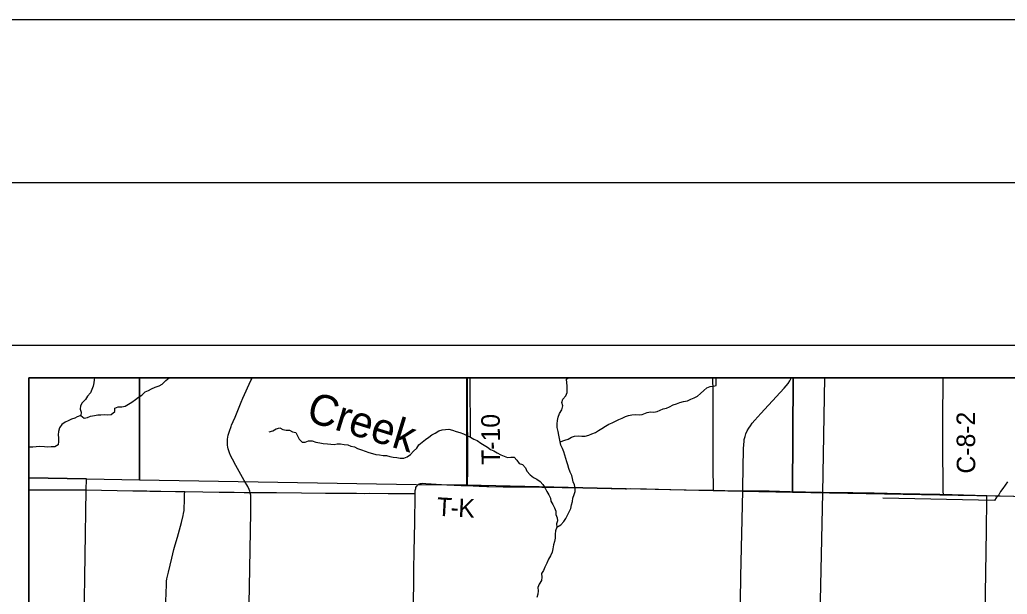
# Model space of a CAD drawing. Extents: x -21.7 to 34, y 0 to 22.
# Drawn here: x 23.488 to 26.522, y 20.235 to 22 of the extents above; entities that cross this region are included whole.
import ezdxf

# ---------------------------------------------------------------- set-up
doc = ezdxf.new("R2010")
doc.units = 0
for name, color, linetype in [('Default', 7, 'Continuous'), ('GM_X_County_Road', 7, 'Continuous'), ('GM_X_County_Road_Text', 7, 'Continuous'), ('GM_X_Interchange_Ramps', 7, 'Continuous'), ('GM_X_Minor_River', 7, 'Continuous'), ('GM_X_Minor_River_Text', 7, 'Continuous'), ('GM_X_Rail_Line', 7, 'Continuous'), ('GM_X_State_Route', 7, 'Continuous'), ('GM_X_Township_Road', 7, 'Continuous'), ('GM_X_Township_Road_Text', 7, 'Continuous'), ('SH_Border', 7, 'Continuous'), ('SH_Cut_Line', 7, 'Continuous'), ('SH_Data', 7, 'Continuous')]:
    doc.layers.add(name, color=color, linetype=linetype)

msp = doc.modelspace()

# ---------------------------------------------------------------- linework, layer by layer
at = {"layer": 'Default'}
for points in [[(23.856, 20.9), (23.5167, 20.9), (23.5167, 20.5927), (23.6932, 20.5898), (23.8561, 20.5869)], [(24.8623, 20.9), (23.856, 20.9), (23.8561, 20.5869), (24.7067, 20.5725), (24.8624, 20.5713)], [(25.8643, 20.9), (24.8623, 20.9), (24.8624, 20.5713), (25.7076, 20.5517), (25.8621, 20.5483)], [(26.8675, 20.9), (25.8643, 20.9), (25.8621, 20.5483), (26.7115, 20.5335), (26.8676, 20.5312)], [(23.5167, 20.5927), (23.5167, 20.5562), (23.693, 20.5545), (23.6932, 20.5898)], [(23.5167, 20.5562), (23.5167, 19.5535), (23.6774, 19.5512), (23.693, 20.5545)]]:
    msp.add_lwpolyline(points, close=True, dxfattribs=at)
at = {"layer": 'GM_X_County_Road'}
for points in [[(24.1961, 20.5478), (24.195, 20.5512), (24.1928, 20.5571), (24.1887, 20.5656), (24.1779, 20.5848), (24.1519, 20.6308), (24.1416, 20.6499), (24.136, 20.661), (24.1324, 20.6695), (24.1305, 20.6753), (24.1289, 20.6813), (24.1276, 20.6873), (24.1268, 20.6934), (24.1264, 20.6995), (24.1264, 20.7057), (24.1267, 20.7118), (24.1275, 20.7179), (24.1288, 20.7239), (24.1324, 20.7359), (24.1376, 20.7499), (24.1389, 20.7547), (24.1439, 20.7656), (24.1499, 20.7789), (24.1582, 20.7996), (24.1682, 20.8247), (24.1743, 20.8369), (24.1987, 20.8912), (24.201, 20.8971), (24.2022, 20.9)], [(26.326, 20.5418), (26.3254, 20.5503), (26.325, 20.5565), (26.3242, 20.6933), (26.3241, 20.768), (26.325, 20.9)], [(24.7034, 20.5441), (24.7034, 20.5493), (24.7033, 20.551), (24.7035, 20.5536), (24.7039, 20.5566), (24.7048, 20.5598), (24.7058, 20.5629), (24.7072, 20.5658), (24.709, 20.5685), (24.7103, 20.5698)], [(24.7103, 20.5698), (24.7113, 20.5709), (24.7139, 20.5728), (24.7169, 20.5742), (24.72, 20.5751), (24.7232, 20.5756), (24.7263, 20.5758), (24.7357, 20.5756), (24.8003, 20.5714), (24.8443, 20.5695), (24.8641, 20.5686)], [(23.5167, 20.5567), (23.6055, 20.556), (23.6583, 20.5553), (23.7391, 20.5543), (23.8355, 20.5527), (23.8634, 20.5524), (23.8789, 20.5523), (23.8882, 20.5521), (23.8913, 20.552), (23.9222, 20.5515), (23.9673, 20.5507), (23.9953, 20.5503)], [(23.9953, 20.5503), (24.0511, 20.5497), (24.1008, 20.549), (24.1253, 20.5485), (24.147, 20.5482), (24.178, 20.548), (24.1961, 20.5478)], [(24.1832, 19.6003), (24.1843, 19.6442), (24.1852, 19.7126), (24.186, 19.7685), (24.187, 19.8244), (24.1894, 19.9642), (24.1905, 20.0482), (24.1917, 20.1134), (24.194, 20.2563), (24.1969, 20.4303), (24.198, 20.4862), (24.1988, 20.5298), (24.1984, 20.5361), (24.198, 20.5392), (24.1968, 20.5453), (24.1961, 20.5478)], [(24.1961, 20.5478), (24.237, 20.5475), (24.2769, 20.5471), (24.3539, 20.5462), (24.4276, 20.5459), (24.4552, 20.5456), (24.5228, 20.5453), (24.5478, 20.5449), (24.5643, 20.5452), (24.6201, 20.545), (24.6461, 20.5445), (24.6953, 20.5442), (24.7034, 20.5441)], [(24.8641, 20.5686), (24.8816, 20.5679), (24.8938, 20.5678), (24.8998, 20.5675), (24.9055, 20.567), (24.9237, 20.5665), (24.9268, 20.5665), (24.9296, 20.5661), (24.9731, 20.5655), (25.0293, 20.5652), (25.2188, 20.5615), (25.3494, 20.559), (25.3525, 20.559), (25.3647, 20.5595), (25.3957, 20.559), (25.4144, 20.5584), (25.489, 20.5572), (25.5355, 20.5562), (25.6198, 20.5546)], [(25.6198, 20.5546), (25.6908, 20.5532), (25.7094, 20.5531)], [(25.7094, 20.5531), (25.7157, 20.5531), (25.7468, 20.5528), (25.7903, 20.5522), (25.8556, 20.5506), (25.9022, 20.5499), (25.9519, 20.5487), (26.0016, 20.548), (26.0482, 20.5472), (26.1135, 20.5465), (26.1943, 20.545), (26.2534, 20.5435), (26.3155, 20.542), (26.326, 20.5418)], [(26.326, 20.5418), (26.3528, 20.5413), (26.4584, 20.5382), (26.4593, 20.5382)], [(26.433, 19.5159), (26.434, 19.5982), (26.4362, 19.7226), (26.4372, 19.7662), (26.439, 19.8066), (26.4419, 19.8594), (26.447, 19.9526), (26.4512, 20.0334), (26.4559, 20.1203), (26.4565, 20.1421), (26.4565, 20.1607), (26.4554, 20.204), (26.4556, 20.2383), (26.4562, 20.3005), (26.4581, 20.4311), (26.4592, 20.5276), (26.4593, 20.5382)], [(26.4593, 20.5382), (26.5424, 20.5362), (26.7039, 20.5311), (26.7598, 20.5304), (26.8158, 20.5296), (26.8674, 20.5283)]]:
    msp.add_lwpolyline(points, dxfattribs=at)
at = {"layer": 'GM_X_Interchange_Ramps'}
msp.add_lwpolyline([(27.8768, 20.9), (23.5167, 20.9), (23.5167, 18.5138)], dxfattribs=at)
at = {"layer": 'GM_X_Minor_River'}
for p, q in [((24.8729, 20.7176), (24.8724, 20.9)), ((25.6283, 20.8768), (25.6281, 20.9))]:
    msp.add_line(p, q, dxfattribs=at)
for points in [[(23.7186, 20.9), (23.7172, 20.894), (23.7158, 20.8841), (23.7141, 20.8743), (23.7104, 20.8641), (23.7056, 20.8536), (23.697, 20.8439), (23.69, 20.8334), (23.6806, 20.8234), (23.6755, 20.8136), (23.6741, 20.8038), (23.6769, 20.7943), (23.6763, 20.784), (23.686, 20.7762), (23.6966, 20.7779), (23.7062, 20.7818), (23.7176, 20.7839), (23.7279, 20.7863), (23.7374, 20.7865), (23.7488, 20.7877), (23.759, 20.786), (23.7693, 20.7876), (23.7805, 20.7969), (23.7804, 20.8068), (23.7907, 20.8103), (23.8025, 20.8112), (23.8124, 20.8129), (23.8228, 20.8187), (23.8324, 20.825), (23.8436, 20.8331), (23.8537, 20.8408), (23.8637, 20.8467), (23.8741, 20.8567), (23.8837, 20.8614), (23.8937, 20.8657), (23.9048, 20.8712), (23.9163, 20.8751), (23.9263, 20.8809), (23.9372, 20.8921), (23.9476, 20.8998), (23.9484, 20.9)], [(25.1388, 20.4406), (25.1503, 20.4483), (25.16, 20.458), (25.166, 20.4681), (25.1708, 20.4779), (25.1763, 20.4884), (25.1811, 20.4989), (25.1833, 20.5098), (25.1866, 20.52), (25.1876, 20.5306), (25.1916, 20.5412), (25.1945, 20.551), (25.1944, 20.5612), (25.1923, 20.5708), (25.1887, 20.5803), (25.1867, 20.5906), (25.1843, 20.6002), (25.1799, 20.6097), (25.1757, 20.6216), (25.1725, 20.6323), (25.1693, 20.6419), (25.1658, 20.6522), (25.1626, 20.6625), (25.1598, 20.6725), (25.1559, 20.6832), (25.1512, 20.6931), (25.1484, 20.7031), (25.1471, 20.7137), (25.1447, 20.7233), (25.1427, 20.7351), (25.1399, 20.7469), (25.1394, 20.7583), (25.1405, 20.7689), (25.143, 20.7795), (25.147, 20.79), (25.1541, 20.802), (25.1567, 20.8134), (25.1543, 20.824), (25.1568, 20.8346), (25.1665, 20.8446), (25.1698, 20.8544), (25.17, 20.8651), (25.1699, 20.8753), (25.1694, 20.8848), (25.1685, 20.8955), (25.1734, 20.9)], [(25.1484, 20.7031), (25.1633, 20.7081), (25.1736, 20.7116), (25.1832, 20.7171), (25.1932, 20.7203), (25.2035, 20.7216), (25.2148, 20.7202), (25.2251, 20.7203), (25.2365, 20.7239), (25.2465, 20.7275), (25.2568, 20.7322), (25.2665, 20.7384), (25.2768, 20.7439), (25.2884, 20.7512), (25.298, 20.7574), (25.308, 20.7618), (25.3183, 20.7665), (25.3291, 20.7719), (25.3394, 20.7755), (25.3494, 20.7813), (25.359, 20.7838), (25.3693, 20.7862), (25.3807, 20.7875), (25.3909, 20.7861), (25.4004, 20.7874), (25.4165, 20.7935), (25.426, 20.7956), (25.4366, 20.7946), (25.4462, 20.7966), (25.4557, 20.801), (25.4653, 20.8046), (25.4749, 20.807), (25.4848, 20.811), (25.4956, 20.8172), (25.5059, 20.8204), (25.5166, 20.8239), (25.5277, 20.8275), (25.5395, 20.8295), (25.5502, 20.8342), (25.5602, 20.8385), (25.5702, 20.8432), (25.5802, 20.8513), (25.59, 20.861), (25.5996, 20.8695), (25.6096, 20.8731), (25.6202, 20.874), (25.6283, 20.8768)], [(23.6763, 20.784), (23.6649, 20.7801), (23.6579, 20.7761), (23.6479, 20.7729), (23.6376, 20.7682), (23.628, 20.7635), (23.618, 20.7569), (23.6101, 20.746), (23.6076, 20.7351), (23.6066, 20.7252), (23.6079, 20.7153), (23.608, 20.7043), (23.6062, 20.6945), (23.5962, 20.6879), (23.5848, 20.6874), (23.5742, 20.6865), (23.564, 20.6874), (23.5492, 20.6885), (23.5393, 20.6876), (23.529, 20.6867), (23.5184, 20.6866), (23.5167, 20.6864)], [(24.2552, 20.7336), (24.2655, 20.7368), (24.2767, 20.7433), (24.2874, 20.7465), (24.2971, 20.7414), (24.3073, 20.7392), (24.3168, 20.7394), (24.3266, 20.7343), (24.3367, 20.7321), (24.3422, 20.7214), (24.3465, 20.711), (24.3561, 20.7021), (24.3656, 20.7023), (24.376, 20.7066), (24.387, 20.706), (24.3979, 20.7019), (24.4104, 20.7001), (24.4209, 20.6984), (24.4338, 20.697), (24.444, 20.6956), (24.4539, 20.6954), (24.4638, 20.6974), (24.474, 20.6972), (24.4854, 20.6954), (24.4963, 20.6937), (24.5061, 20.6904), (24.5167, 20.6883), (24.5264, 20.6831), (24.5385, 20.6787), (24.5497, 20.6743), (24.5614, 20.6706), (24.5723, 20.6673), (24.5825, 20.6648), (24.5935, 20.6634), (24.6045, 20.6613), (24.6151, 20.661), (24.6252, 20.6578), (24.6358, 20.6557), (24.6468, 20.655), (24.657, 20.6533), (24.6688, 20.6534), (24.6787, 20.657), (24.6884, 20.6647), (24.6981, 20.6744), (24.7082, 20.6837), (24.7149, 20.6945), (24.7246, 20.7023), (24.735, 20.71), (24.745, 20.7178), (24.7547, 20.7251), (24.7647, 20.7302), (24.7758, 20.7372), (24.7858, 20.74), (24.796, 20.7413), (24.8063, 20.7418), (24.8184, 20.7389), (24.8289, 20.7349), (24.8402, 20.732), (24.8515, 20.7275), (24.862, 20.7227), (24.8729, 20.7176), (24.8834, 20.7113), (24.8939, 20.7069), (24.9047, 20.699), (24.9148, 20.6935), (24.9253, 20.6868), (24.935, 20.6801), (24.9448, 20.6761), (24.9552, 20.6698), (24.9665, 20.6635), (24.9762, 20.6587), (24.9868, 20.6554), (24.997, 20.656), (25.0077, 20.6565), (25.0158, 20.6468), (25.0227, 20.6368), (25.0329, 20.6331), (25.0422, 20.6231), (25.0461, 20.6131), (25.0568, 20.6019), (25.0669, 20.594), (25.077, 20.5885), (25.0871, 20.5815), (25.0952, 20.5718), (25.1029, 20.5614), (25.1076, 20.5502), (25.1134, 20.5402), (25.1189, 20.5306), (25.1202, 20.5211), (25.1264, 20.5111), (25.1311, 20.5008), (25.135, 20.4904), (25.1355, 20.4805), (25.1395, 20.4702), (25.1408, 20.4607), (25.1379, 20.4509), (25.1388, 20.4406), (25.1347, 20.4297), (25.1337, 20.4195), (25.1338, 20.4077), (25.1313, 20.3975)], [(26.5231, 20.5801), (26.5157, 20.57), (26.5083, 20.5603), (26.5019, 20.5502), (26.496, 20.5405), (26.4882, 20.5308), (26.4835, 20.5233)], [(26.4835, 20.5233), (26.1403, 20.5298)], [(25.1313, 20.3975), (25.1284, 20.3866), (25.1266, 20.3748), (25.1241, 20.3646), (25.1185, 20.3534), (25.1133, 20.3429), (25.1073, 20.3308), (25.1021, 20.3181), (25.0977, 20.3083), (25.0918, 20.2985), (25.0919, 20.2879), (25.0913, 20.2769), (25.0842, 20.2664), (25.0805, 20.2555), (25.081, 20.2453), (25.08, 20.2354), (25.0775, 20.2252)]]:
    msp.add_lwpolyline(points, dxfattribs=at)
at = {"layer": 'GM_X_Rail_Line'}
msp.add_lwpolyline([(25.8368, 14.1), (25.8424, 14.4841), (25.8672, 15.4825), (25.8776, 16.2603), (25.8795, 16.4862), (25.8906, 16.927), (25.8907, 16.9438), (25.8961, 17.4845), (25.9239, 18.7551), (25.935, 19.5978), (25.9554, 20.5461), (25.9616, 20.9)], dxfattribs=at)
at = {"layer": 'GM_X_State_Route'}
msp.add_lwpolyline([(25.7012, 20.1404), (25.7041, 20.2896), (25.7094, 20.5531), (25.7096, 20.564), (25.7119, 20.6821), (25.7125, 20.6946), (25.7135, 20.7039), (25.7145, 20.7101), (25.7167, 20.7192), (25.7196, 20.7282), (25.7234, 20.7368), (25.7279, 20.745), (25.7331, 20.7529), (25.7387, 20.7604), (25.7467, 20.77), (25.7655, 20.7908), (25.8246, 20.8547), (25.8373, 20.8683), (25.8433, 20.8754), (25.849, 20.8827), (25.8542, 20.8904), (25.8588, 20.8984), (25.8595, 20.9)], dxfattribs=at)
at = {"layer": 'GM_X_Township_Road'}
for points in [[(24.8641, 20.5686), (24.8643, 20.5761), (24.8649, 20.6134), (24.8651, 20.6942), (24.8641, 20.7719), (24.8639, 20.8341), (24.8638, 20.9)], [(25.6198, 20.5546), (25.6197, 20.5598), (25.6195, 20.566), (25.6191, 20.6157), (25.6191, 20.6901), (25.6189, 20.7646), (25.6183, 20.8577), (25.6178, 20.9)], [(24.7034, 20.5441), (24.7034, 20.5493), (24.7033, 20.551), (24.7035, 20.5536), (24.7039, 20.5566), (24.7048, 20.5598), (24.7058, 20.5629), (24.7072, 20.5658), (24.709, 20.5685), (24.7103, 20.5698)], [(24.7103, 20.5698), (24.7113, 20.5709), (24.7139, 20.5728), (24.7169, 20.5742), (24.72, 20.5751), (24.7232, 20.5756), (24.7263, 20.5758), (24.7357, 20.5756), (24.8003, 20.5714), (24.8443, 20.5695), (24.8641, 20.5686)], [(23.5167, 20.5567), (23.6055, 20.556), (23.6583, 20.5553), (23.7391, 20.5543), (23.8355, 20.5527), (23.8634, 20.5524), (23.8789, 20.5523), (23.8882, 20.5521), (23.8913, 20.552), (23.9222, 20.5515), (23.9673, 20.5507), (23.9953, 20.5503)], [(23.9377, 20.2094), (23.9387, 20.2422), (23.9392, 20.2604), (23.9395, 20.2679), (23.9398, 20.2756), (23.9406, 20.2828), (23.9426, 20.2908), (23.9452, 20.3031), (23.9552, 20.3454), (23.9622, 20.3724), (23.9663, 20.3871), (23.9727, 20.4108), (23.9855, 20.4556), (23.9909, 20.4767), (23.992, 20.4828), (23.9932, 20.4922), (23.9937, 20.5015), (23.9943, 20.5202), (23.995, 20.5419), (23.9953, 20.5503)], [(23.9953, 20.5503), (24.0511, 20.5497), (24.1008, 20.549), (24.1253, 20.5485), (24.147, 20.5482), (24.178, 20.548), (24.1961, 20.5478)], [(24.1961, 20.5478), (24.237, 20.5475), (24.2769, 20.5471), (24.3539, 20.5462), (24.4276, 20.5459), (24.4552, 20.5456), (24.5228, 20.5453), (24.5478, 20.5449), (24.5643, 20.5452), (24.6201, 20.545), (24.6461, 20.5445), (24.6953, 20.5442), (24.7034, 20.5441)], [(24.69, 19.7638), (24.69, 19.7731), (24.6917, 19.882), (24.6937, 20.0126), (24.6988, 20.2673), (24.6995, 20.3171), (24.7004, 20.3606), (24.7013, 20.4166), (24.7021, 20.4508), (24.7034, 20.5441)], [(24.8641, 20.5686), (24.8816, 20.5679), (24.8938, 20.5678), (24.8998, 20.5675), (24.9055, 20.567), (24.9237, 20.5665), (24.9268, 20.5665), (24.9296, 20.5661), (24.9731, 20.5655), (25.0293, 20.5652), (25.2188, 20.5615), (25.3494, 20.559), (25.3525, 20.559), (25.3647, 20.5595), (25.3957, 20.559), (25.4144, 20.5584), (25.489, 20.5572), (25.5355, 20.5562), (25.6198, 20.5546)], [(25.6198, 20.5546), (25.6908, 20.5532), (25.7094, 20.5531)], [(25.7094, 20.5531), (25.7157, 20.5531), (25.7468, 20.5528), (25.7903, 20.5522), (25.8556, 20.5506), (25.9022, 20.5499), (25.9519, 20.5487), (26.0016, 20.548), (26.0482, 20.5472), (26.1135, 20.5465), (26.1943, 20.545), (26.2534, 20.5435), (26.3155, 20.542), (26.326, 20.5418)]]:
    msp.add_lwpolyline(points, dxfattribs=at)
at = {"layer": 'SH_Border'}
msp.add_lwpolyline([(1.5, 21.5), (33.5, 21.5), (33.5, 0.5), (1.5, 0.5)], close=True, dxfattribs=at)
at = {"layer": 'SH_Cut_Line'}
msp.add_lwpolyline([(0, 0), (34, 0), (34, 22), (0, 22)], close=True, dxfattribs=at)
at = {"layer": 'SH_Data'}
for q in [(23.5167, 14.1), (30.3167, 20.9)]:
    msp.add_line((23.5167, 20.9), q, dxfattribs=at)
for points in [[(23.4167, 21), (30.4167, 21), (30.4167, 14), (23.4167, 14)], [(23.5167, 20.9), (30.3167, 20.9), (30.3167, 14.1), (23.5167, 14.1)]]:
    msp.add_lwpolyline(points, close=True, dxfattribs=at)

# ---------------------------------------------------------------- texts
at = {"layer": 'GM_X_County_Road_Text'}
msp.add_text('C-8-2', height=0.05682, rotation=90.2952, dxfattribs=at).set_placement((26.4241, 20.6059))
at = {"layer": 'GM_X_Minor_River_Text'}
msp.add_text('Creek', height=0.09476, rotation=343.0229, dxfattribs=at).set_placement((24.3647, 20.7685))
at = {"layer": 'GM_X_Township_Road_Text'}
for s, height, rotation, p in [('T-10', 0.05682, 90.3537, (24.964, 20.6329)), ('T', 0.0568, 356.8958, (24.7684, 20.4762)), ('K', 0.0568, 357.2924, (24.8346, 20.4726)), ('-', 0.0568, 356.9308, (24.8109, 20.4739))]:
    msp.add_text(s, height=height, rotation=rotation, dxfattribs=at).set_placement(p)

doc.saveas('drawing.dxf')
